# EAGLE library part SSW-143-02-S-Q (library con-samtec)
THROUGH-HOLE .025" SQ POST SOCKET Source: Samtec SSW.pdf
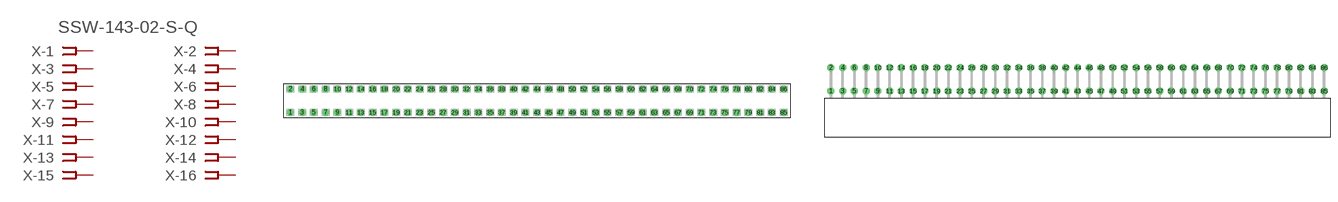
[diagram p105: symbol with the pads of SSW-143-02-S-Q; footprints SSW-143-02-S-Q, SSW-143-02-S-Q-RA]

Designator prefix X; gates -1=FPINV -2=FPIN -3=FPIN -4=FPIN -5=FPIN -6=FPIN -7=FPIN -8=FPIN -9=FPIN -10=FPIN -11=FPIN -12=FPIN -13=FPIN -14=FPIN -15=FPIN -16=FPIN -17=FPIN -18=FPIN -19=FPIN -20=FPIN -21=FPIN -22=FPIN -23=FPIN -24=FPIN -25=FPIN -26=FPIN -27=FPIN -28=FPIN -29=FPIN -30=FPIN -31=FPIN -32=FPIN -33=FPIN -34=FPIN -35=FPIN -36=FPIN -37=FPIN -38=FPIN -39=FPIN -40=FPIN -41=FPIN -42=FPIN -43=FPIN -44=FPIN -45=FPIN -46=FPIN -47=FPIN -48=FPIN -49=FPIN -50=FPIN -51=FPIN -52=FPIN -53=FPIN -54=FPIN -55=FPIN -56=FPIN -57=FPIN -58=FPIN -59=FPIN -60=FPIN -61=FPIN -62=FPIN -63=FPIN -64=FPIN -65=FPIN -66=FPIN -67=FPIN -68=FPIN -69=FPIN -70=FPIN -71=FPIN -72=FPIN -73=FPIN -74=FPIN -75=FPIN -76=FPIN -77=FPIN -78=FPIN -79=FPIN -80=FPIN -81=FPIN -82=FPIN -83=FPIN -84=FPIN -85=FPIN -86=FPIN

## SSW-143-02-S-Q (OC_FARNELL: unknown; OC_NEWARK: unknown)  [SSW-143-02-S-Q]
1  -1:1  pas
2  -2:1  pas
3  -3:1  pas
4  -4:1  pas
5  -5:1  pas
6  -6:1  pas
7  -7:1  pas
8  -8:1  pas
9  -9:1  pas
10  -10:1  pas
11  -11:1  pas
12  -12:1  pas
13  -13:1  pas
14  -14:1  pas
15  -15:1  pas
16  -16:1  pas
17  -17:1  pas
18  -18:1  pas
19  -19:1  pas
20  -20:1  pas
21  -21:1  pas
22  -22:1  pas
23  -23:1  pas
24  -24:1  pas
25  -25:1  pas
26  -26:1  pas
27  -27:1  pas
28  -28:1  pas
29  -29:1  pas
30  -30:1  pas
31  -31:1  pas
32  -32:1  pas
33  -33:1  pas
34  -34:1  pas
35  -35:1  pas
36  -36:1  pas
37  -37:1  pas
38  -38:1  pas
39  -39:1  pas
40  -40:1  pas
41  -41:1  pas
42  -42:1  pas
43  -43:1  pas
44  -44:1  pas
45  -45:1  pas
46  -46:1  pas
47  -47:1  pas
48  -48:1  pas
49  -49:1  pas
50  -50:1  pas
51  -51:1  pas
52  -52:1  pas
53  -53:1  pas
54  -54:1  pas
55  -55:1  pas
56  -56:1  pas
57  -57:1  pas
58  -58:1  pas
59  -59:1  pas
60  -60:1  pas
61  -61:1  pas
62  -62:1  pas
63  -63:1  pas
64  -64:1  pas
65  -65:1  pas
66  -66:1  pas
67  -67:1  pas
68  -68:1  pas
69  -69:1  pas
70  -70:1  pas
71  -71:1  pas
72  -72:1  pas
73  -73:1  pas
74  -74:1  pas
75  -75:1  pas
76  -76:1  pas
77  -77:1  pas
78  -78:1  pas
79  -79:1  pas
80  -80:1  pas
81  -81:1  pas
82  -82:1  pas
83  -83:1  pas
84  -84:1  pas
85  -85:1  pas
86  -86:1  pas

## SSW-143-02-S-QRA (OC_FARNELL: unknown; OC_NEWARK: unknown)  [SSW-143-02-S-Q-RA]
Pads as for SSW-143-02-S-Q

## Footprint SSW-143-02-S-Q (pad centres in mm)
THROUGH-HOLE .025" SQ POST SOCKET Source: Samtec SSW.pdf
drill 1 pad 1.5 octagon: 1 -53.34,-2.54; 2 -53.34,2.54; 3 -50.8,-2.54; 4 -50.8,2.54; 5 -48.26,-2.54; 6 -48.26,2.54; 7 -45.72,-2.54; 8 -45.72,2.54; 9 -43.18,-2.54; 10 -43.18,2.54; 11 -40.64,-2.54; 12 -40.64,2.54; 13 -38.1,-2.54; 14 -38.1,2.54; 15 -35.56,-2.54; 16 -35.56,2.54; 17 -33.02,-2.54; 18 -33.02,2.54; 19 -30.48,-2.54; 20 -30.48,2.54; 21 -27.94,-2.54; 22 -27.94,2.54; 23 -25.4,-2.54; 24 -25.4,2.54; 25 -22.86,-2.54; 26 -22.86,2.54; 27 -20.32,-2.54; 28 -20.32,2.54; 29 -17.78,-2.54; 30 -17.78,2.54; 31 -15.24,-2.54; 32 -15.24,2.54; 33 -12.7,-2.54; 34 -12.7,2.54; 35 -10.16,-2.54; 36 -10.16,2.54; 37 -7.62,-2.54; 38 -7.62,2.54; 39 -5.08,-2.54; 40 -5.08,2.54; 41 -2.54,-2.54; 42 -2.54,2.54; 43 0,-2.54; 44 0,2.54; 45 2.54,-2.54; 46 2.54,2.54; 47 5.08,-2.54; 48 5.08,2.54; 49 7.62,-2.54; 50 7.62,2.54; 51 10.16,-2.54; 52 10.16,2.54; 53 12.7,-2.54; 54 12.7,2.54; 55 15.24,-2.54; 56 15.24,2.54; 57 17.78,-2.54; 58 17.78,2.54; 59 20.32,-2.54; 60 20.32,2.54; 61 22.86,-2.54; 62 22.86,2.54; 63 25.4,-2.54; 64 25.4,2.54; 65 27.94,-2.54; 66 27.94,2.54; 67 30.48,-2.54; 68 30.48,2.54; 69 33.02,-2.54; 70 33.02,2.54; 71 35.56,-2.54; 72 35.56,2.54; 73 38.1,-2.54; 74 38.1,2.54; 75 40.64,-2.54; 76 40.64,2.54; 77 43.18,-2.54; 78 43.18,2.54; 79 45.72,-2.54; 80 45.72,2.54; 81 48.26,-2.54; 82 48.26,2.54; 83 50.8,-2.54; 84 50.8,2.54; 85 53.34,-2.54; 86 53.34,2.54

## Footprint SSW-143-02-S-Q-RA (pad centres in mm)
THROUGH-HOLE .025" SQ POST SOCKET Source: Samtec SSW.pdf
drill 1 pad 1.5 octagon: 1 -53.34,1.524; 2 -53.34,6.604; 3 -50.8,1.524; 4 -50.8,6.604; 5 -48.26,1.524; 6 -48.26,6.604; 7 -45.72,1.524; 8 -45.72,6.604; 9 -43.18,1.524; 10 -43.18,6.604; 11 -40.64,1.524; 12 -40.64,6.604; 13 -38.1,1.524; 14 -38.1,6.604; 15 -35.56,1.524; 16 -35.56,6.604; 17 -33.02,1.524; 18 -33.02,6.604; 19 -30.48,1.524; 20 -30.48,6.604; 21 -27.94,1.524; 22 -27.94,6.604; 23 -25.4,1.524; 24 -25.4,6.604; 25 -22.86,1.524; 26 -22.86,6.604; 27 -20.32,1.524; 28 -20.32,6.604; 29 -17.78,1.524; 30 -17.78,6.604; 31 -15.24,1.524; 32 -15.24,6.604; 33 -12.7,1.524; 34 -12.7,6.604; 35 -10.16,1.524; 36 -10.16,6.604; 37 -7.62,1.524; 38 -7.62,6.604; 39 -5.08,1.524; 40 -5.08,6.604; 41 -2.54,1.524; 42 -2.54,6.604; 43 0,1.524; 44 0,6.604; 45 2.54,1.524; 46 2.54,6.604; 47 5.08,1.524; 48 5.08,6.604; 49 7.62,1.524; 50 7.62,6.604; 51 10.16,1.524; 52 10.16,6.604; 53 12.7,1.524; 54 12.7,6.604; 55 15.24,1.524; 56 15.24,6.604; 57 17.78,1.524; 58 17.78,6.604; 59 20.32,1.524; 60 20.32,6.604; 61 22.86,1.524; 62 22.86,6.604; 63 25.4,1.524; 64 25.4,6.604; 65 27.94,1.524; 66 27.94,6.604; 67 30.48,1.524; 68 30.48,6.604; 69 33.02,1.524; 70 33.02,6.604; 71 35.56,1.524; 72 35.56,6.604; 73 38.1,1.524; 74 38.1,6.604; 75 40.64,1.524; 76 40.64,6.604; 77 43.18,1.524; 78 43.18,6.604; 79 45.72,1.524; 80 45.72,6.604; 81 48.26,1.524; 82 48.26,6.604; 83 50.8,1.524; 84 50.8,6.604; 85 53.34,1.524; 86 53.34,6.604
